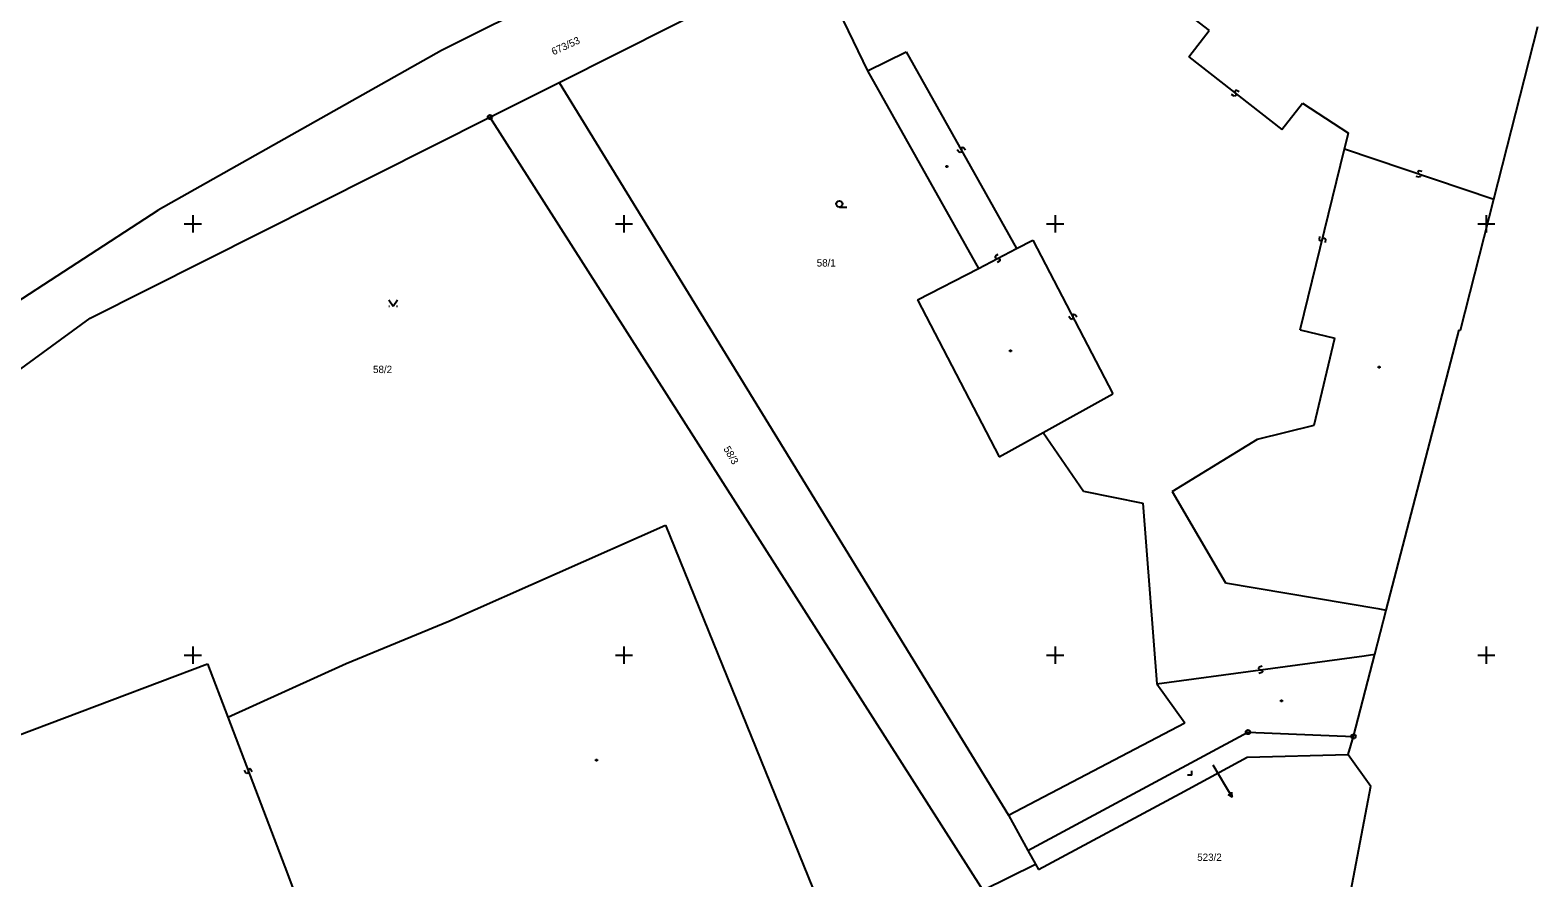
# Model space of a CAD drawing. Extents: x -492811 to -492366, y -1127107 to -1126748.
# Drawn here: x -492547.5 to -492477.6, y -1126990.3 to -1126951 of the extents above; entities that cross this region are included whole.
import ezdxf

# ---------------------------------------------------------------- set-up
doc = ezdxf.new("R2010")
doc.units = 0
doc.layers.add('katastrální mapa', color=7, linetype='Continuous')
doc.layers.add('síť', color=7, linetype='Continuous')

msp = doc.modelspace()

# ---------------------------------------------------------------- linework, layer by layer
at = {"layer": 'katastrální mapa'}
for p, q in [((-492506.11, -1126940.81), (-492528.47, -1126951.96)), ((-492523, -1126953.44), (-492510.45, -1126947.13)), ((-492496.59, -1126948.15), (-492492.85, -1126951.04)), ((-492510.27, -1126949.68), (-492508.71, -1126952.9)), ((-492493.8, -1126952.26), (-492492.85, -1126951.04)), ((-492479.65, -1126958.85), (-492477.61, -1126950.85)), ((-492528.47, -1126951.96), (-492541.6, -1126959.36)), ((-492508.71, -1126952.9), (-492506.91, -1126952.02)), ((-492506.91, -1126952.02), (-492501.79, -1126961.14)), ((-492493.8, -1126952.26), (-492489.48, -1126955.63)), ((-492526.22, -1126955.05), (-492523, -1126953.44)), ((-492523, -1126953.44), (-492502.17, -1126987.42)), ((-492508.71, -1126952.9), (-492503.56, -1126962.07)), ((-492491.69, -1126954.08), (-492491.82, -1126954.01)), ((-492491.64, -1126954.07), (-492491.69, -1126954.08)), ((-492491.64, -1126953.82), (-492491.67, -1126953.85)), ((-492491.67, -1126953.85), (-492491.66, -1126953.9)), ((-492491.66, -1126953.9), (-492491.62, -1126953.99)), ((-492491.59, -1126953.81), (-492491.64, -1126953.82)), ((-492491.61, -1126954.04), (-492491.64, -1126954.07)), ((-492491.62, -1126953.99), (-492491.61, -1126954.04)), ((-492491.46, -1126953.88), (-492491.59, -1126953.81)), ((-492489.48, -1126955.63), (-492488.53, -1126954.41)), ((-492488.53, -1126954.41), (-492486.4, -1126955.8)), ((-492544.76, -1126964.37), (-492526.22, -1126955.05)), ((-492526.22, -1126955.05), (-492503.36, -1126990.89)), ((-492486.58, -1126956.52), (-492486.4, -1126955.8)), ((-492504.45, -1126956.68), (-492504.54, -1126956.57)), ((-492504.4, -1126956.7), (-492504.45, -1126956.68)), ((-492504.36, -1126956.68), (-492504.4, -1126956.7)), ((-492504.35, -1126956.62), (-492504.36, -1126956.68)), ((-492504.34, -1126956.48), (-492504.35, -1126956.54)), ((-492504.35, -1126956.54), (-492504.35, -1126956.62)), ((-492504.3, -1126956.46), (-492504.34, -1126956.48)), ((-492504.25, -1126956.48), (-492504.3, -1126956.46)), ((-492504.16, -1126956.59), (-492504.25, -1126956.48)), ((-492488.64, -1126964.92), (-492486.58, -1126956.52)), ((-492486.58, -1126956.52), (-492479.65, -1126958.85)), ((-492505.06, -1126957.31), (-492505, -1126957.31)), ((-492505.06, -1126957.37), (-492505.06, -1126957.31)), ((-492505, -1126957.37), (-492505.06, -1126957.37)), ((-492505, -1126957.31), (-492505, -1126957.37)), ((-492483.16, -1126957.56), (-492483.17, -1126957.6)), ((-492483.17, -1126957.6), (-492483.15, -1126957.65)), ((-492483.11, -1126957.54), (-492483.16, -1126957.56)), ((-492483.15, -1126957.65), (-492483.08, -1126957.72)), ((-492482.97, -1126957.57), (-492483.11, -1126957.54)), ((-492483.08, -1126957.72), (-492483.06, -1126957.77)), ((-492483.12, -1126957.83), (-492483.26, -1126957.8)), ((-492483.07, -1126957.81), (-492483.12, -1126957.83)), ((-492483.06, -1126957.77), (-492483.07, -1126957.81)), ((-492481.2, -1126964.93), (-492479.65, -1126958.85)), ((-492549.77, -1126964.67), (-492541.6, -1126959.36)), ((-492510.01, -1126959.23), (-492509.66, -1126959.23)), ((-492503.56, -1126962.07), (-492501.79, -1126961.14)), ((-492501.79, -1126961.14), (-492501.03, -1126960.75)), ((-492501.03, -1126960.75), (-492497.33, -1126967.88)), ((-492487.74, -1126960.58), (-492487.76, -1126960.73)), ((-492487.76, -1126960.73), (-492487.73, -1126960.77)), ((-492487.73, -1126960.77), (-492487.69, -1126960.78)), ((-492487.69, -1126960.78), (-492487.64, -1126960.75)), ((-492487.64, -1126960.75), (-492487.58, -1126960.69)), ((-492487.58, -1126960.69), (-492487.53, -1126960.66)), ((-492487.53, -1126960.66), (-492487.49, -1126960.67)), ((-492487.49, -1126960.67), (-492487.46, -1126960.71)), ((-492487.46, -1126960.71), (-492487.48, -1126960.86)), ((-492502.78, -1126961.5), (-492502.79, -1126961.55)), ((-492502.79, -1126961.55), (-492502.77, -1126961.59)), ((-492502.66, -1126961.42), (-492502.78, -1126961.5)), ((-492502.77, -1126961.59), (-492502.72, -1126961.61)), ((-492502.72, -1126961.61), (-492502.63, -1126961.6)), ((-492502.57, -1126961.71), (-492502.69, -1126961.79)), ((-492502.63, -1126961.6), (-492502.58, -1126961.62)), ((-492502.58, -1126961.62), (-492502.56, -1126961.66)), ((-492502.56, -1126961.66), (-492502.57, -1126961.71)), ((-492506.38, -1126963.53), (-492503.56, -1126962.07)), ((-492530.91, -1126963.52), (-492530.71, -1126963.82)), ((-492530.91, -1126963.82), (-492530.87, -1126963.82)), ((-492530.71, -1126963.82), (-492530.51, -1126963.52)), ((-492530.55, -1126963.82), (-492530.51, -1126963.82)), ((-492506.38, -1126963.53), (-492502.59, -1126970.8)), ((-492564.89, -1126979.09), (-492544.76, -1126964.37)), ((-492499.29, -1126964.41), (-492499.37, -1126964.3)), ((-492499.23, -1126964.43), (-492499.29, -1126964.41)), ((-492499.2, -1126964.41), (-492499.23, -1126964.43)), ((-492499.18, -1126964.36), (-492499.2, -1126964.41)), ((-492499.16, -1126964.22), (-492499.18, -1126964.27)), ((-492499.18, -1126964.27), (-492499.18, -1126964.36)), ((-492499.13, -1126964.2), (-492499.16, -1126964.22)), ((-492499.07, -1126964.22), (-492499.13, -1126964.2)), ((-492498.99, -1126964.33), (-492499.07, -1126964.22)), ((-492488.64, -1126964.92), (-492487.03, -1126965.3)), ((-492487.99, -1126969.34), (-492487.03, -1126965.3)), ((-492484.64, -1126977.91), (-492481.26, -1126964.91)), ((-492481.26, -1126964.91), (-492481.2, -1126964.93)), ((-492502.1, -1126965.86), (-492502.04, -1126965.86)), ((-492502.1, -1126965.92), (-492502.1, -1126965.86)), ((-492502.04, -1126965.92), (-492502.1, -1126965.92)), ((-492502.04, -1126965.86), (-492502.04, -1126965.92)), ((-492485, -1126966.62), (-492484.94, -1126966.62)), ((-492485, -1126966.68), (-492485, -1126966.62)), ((-492484.94, -1126966.68), (-492485, -1126966.68)), ((-492484.94, -1126966.62), (-492484.94, -1126966.68)), ((-492500.56, -1126969.67), (-492497.33, -1126967.88)), ((-492490.61, -1126969.98), (-492487.99, -1126969.34)), ((-492502.59, -1126970.8), (-492500.56, -1126969.67)), ((-492500.56, -1126969.67), (-492498.69, -1126972.4)), ((-492494.57, -1126972.41), (-492490.61, -1126969.98)), ((-492498.69, -1126972.4), (-492495.93, -1126972.95)), ((-492494.57, -1126972.41), (-492492.1, -1126976.65)), ((-492495.93, -1126972.95), (-492495.28, -1126981.33)), ((-492528.12, -1126978.42), (-492518.07, -1126973.98)), ((-492518.07, -1126973.98), (-492509.58, -1126994.89)), ((-492492.1, -1126976.65), (-492485.03, -1126977.84)), ((-492485.17, -1126979.96), (-492484.64, -1126977.91)), ((-492485.03, -1126977.84), (-492484.64, -1126977.91)), ((-492532.89, -1126980.39), (-492528.12, -1126978.42)), ((-492495.28, -1126981.33), (-492485.66, -1126980.03)), ((-492486.16, -1126983.77), (-492485.17, -1126979.96)), ((-492485.66, -1126980.03), (-492485.17, -1126979.96)), ((-492539.32, -1126980.4), (-492538.38, -1126982.88)), ((-492538.38, -1126982.88), (-492532.89, -1126980.39)), ((-492490.53, -1126980.55), (-492490.56, -1126980.59)), ((-492490.56, -1126980.59), (-492490.56, -1126980.63)), ((-492490.56, -1126980.63), (-492490.51, -1126980.67)), ((-492490.41, -1126980.81), (-492490.55, -1126980.85)), ((-492490.39, -1126980.51), (-492490.53, -1126980.55)), ((-492490.51, -1126980.67), (-492490.43, -1126980.69)), ((-492490.43, -1126980.69), (-492490.38, -1126980.73)), ((-492490.38, -1126980.77), (-492490.41, -1126980.81)), ((-492490.38, -1126980.73), (-492490.38, -1126980.77)), ((-492495.28, -1126981.33), (-492493.99, -1126983.14)), ((-492489.53, -1126982.09), (-492489.47, -1126982.09)), ((-492489.53, -1126982.15), (-492489.53, -1126982.09)), ((-492489.47, -1126982.15), (-492489.53, -1126982.15)), ((-492489.47, -1126982.09), (-492489.47, -1126982.15)), ((-492538.38, -1126982.88), (-492536.47, -1126987.87)), ((-492502.17, -1126987.42), (-492493.99, -1126983.14)), ((-492501.26, -1126989.06), (-492491.06, -1126983.57)), ((-492491.06, -1126983.57), (-492486.16, -1126983.77)), ((-492486.41, -1126984.61), (-492486.16, -1126983.77)), ((-492521.3, -1126984.84), (-492521.24, -1126984.84)), ((-492521.3, -1126984.9), (-492521.3, -1126984.84)), ((-492521.24, -1126984.9), (-492521.3, -1126984.9)), ((-492521.24, -1126984.84), (-492521.24, -1126984.9)), ((-492494.2, -1126986.41), (-492491.09, -1126984.73)), ((-492491.09, -1126984.73), (-492486.41, -1126984.61)), ((-492486.41, -1126984.61), (-492485.35, -1126986.07)), ((-492537.54, -1126985.46), (-492537.61, -1126985.34)), ((-492537.49, -1126985.49), (-492537.54, -1126985.46)), ((-492537.45, -1126985.47), (-492537.49, -1126985.49)), ((-492537.43, -1126985.42), (-492537.45, -1126985.47)), ((-492537.42, -1126985.33), (-492537.43, -1126985.42)), ((-492537.4, -1126985.28), (-492537.42, -1126985.33)), ((-492537.36, -1126985.26), (-492537.4, -1126985.28)), ((-492537.31, -1126985.29), (-492537.36, -1126985.26)), ((-492537.24, -1126985.41), (-492537.31, -1126985.29)), ((-492493.66, -1126985.56), (-492493.86, -1126985.56)), ((-492493.66, -1126985.56), (-492493.66, -1126985.36)), ((-492492.69, -1126985.09), (-492492.1, -1126986.07)), ((-492500.77, -1126989.94), (-492494.2, -1126986.41)), ((-492492.1, -1126986.07), (-492491.79, -1126986.58)), ((-492491.79, -1126986.58), (-492491.81, -1126986.36)), ((-492486.71, -1126993.16), (-492485.35, -1126986.07)), ((-492491.79, -1126986.58), (-492491.98, -1126986.46)), ((-492502.17, -1126987.42), (-492501.26, -1126989.06)), ((-492536.47, -1126987.87), (-492535.61, -1126990.14)), ((-492501.26, -1126989.06), (-492500.91, -1126989.69)), ((-492503.36, -1126990.89), (-492500.91, -1126989.69)), ((-492500.91, -1126989.69), (-492500.77, -1126989.94)), ((-492535.61, -1126990.14), (-492533.8, -1126994.89))]:
    msp.add_line(p, q, dxfattribs=at)
msp.add_lwpolyline([(-492567.33, -1126990.97), (-492550.39, -1126984.58), (-492539.32, -1126980.4)], dxfattribs=at)
for centre, radius in [((-492526.22, -1126955.05), 0.1), ((-492526.22, -1126955.05), 0.002), ((-492510.01, -1126959.08), 0.15), ((-492491.06, -1126983.57), 0.1), ((-492491.06, -1126983.57), 0.002), ((-492486.16, -1126983.77), 0.1), ((-492486.16, -1126983.77), 0.002)]:
    msp.add_circle(centre, radius, dxfattribs=at)
at = {"layer": 'síť'}
for p, q in [((-492540, -1126959.6), (-492540, -1126960.4)), ((-492520, -1126959.6), (-492520, -1126960.4)), ((-492500, -1126959.6), (-492500, -1126960.4)), ((-492480, -1126959.6), (-492480, -1126960.4)), ((-492540.4, -1126960), (-492539.6, -1126960)), ((-492520.4, -1126960), (-492519.6, -1126960)), ((-492500.4, -1126960), (-492499.6, -1126960)), ((-492480.4, -1126960), (-492479.6, -1126960)), ((-492540.4, -1126980), (-492539.6, -1126980)), ((-492540, -1126979.6), (-492540, -1126980.4)), ((-492520.4, -1126980), (-492519.6, -1126980)), ((-492520, -1126979.6), (-492520, -1126980.4)), ((-492500.4, -1126980), (-492499.6, -1126980)), ((-492500, -1126979.6), (-492500, -1126980.4)), ((-492480.4, -1126980), (-492479.6, -1126980)), ((-492480, -1126979.6), (-492480, -1126980.4))]:
    msp.add_line(p, q, dxfattribs=at)

# ---------------------------------------------------------------- texts
at = {"layer": 'katastrální mapa'}
for s, rotation, p in [('673/53', 24.57612, (-492523.27, -1126952.19)), ('58/3', 300.114, (-492515.4, -1126970.43))]:
    msp.add_text(s, height=0.34, rotation=rotation, dxfattribs=at).set_placement(p)
for s, height, p in [('58/1', 0.34, (-492511.06, -1126961.98)), ('58/2', 0.34, (-492531.64, -1126966.92)), ('523/2', 0.02, (-492492.69, -1126985.09)), ('523/2', 0.34, (-492493.41, -1126989.54))]:
    msp.add_text(s, height=height, dxfattribs=at).set_placement(p)

doc.saveas('drawing.dxf')
